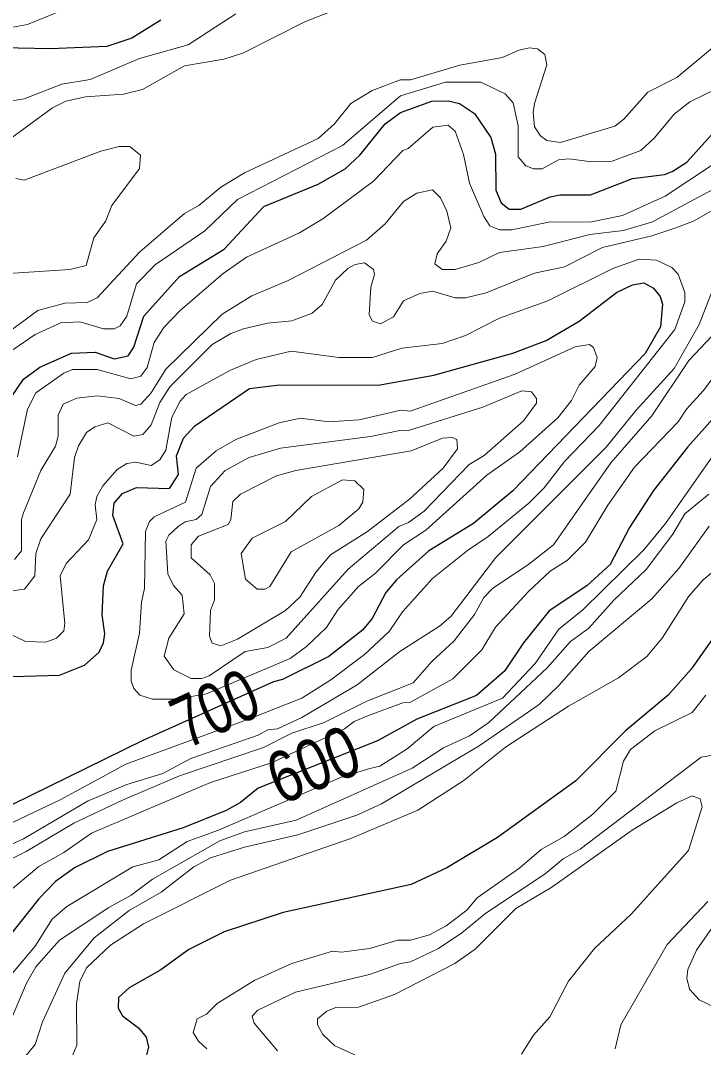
# Model space of a CAD drawing. Extents: x 577 to 602.9, y 7483.8 to 7511.6.
# Drawn here: x 592.28 to 593.349, y 7492.363 to 7493.971 of the extents above; entities that cross this region are included whole.
import ezdxf
from ezdxf.enums import TextEntityAlignment as Align

# ---------------------------------------------------------------- set-up
doc = ezdxf.new("R2010")
doc.units = 0
doc.header["$LTSCALE"] = 0.032
doc.layers.add('1', color=7, linetype='Continuous', lineweight=25)
doc.layers.add('2', color=7, linetype='Continuous', lineweight=13)
doc.layers.add('61', color=7, linetype='Continuous')

msp = doc.modelspace()

# ---------------------------------------------------------------- linework, layer by layer
at = {"layer": '1'}
for points in [[(592.499, 7493.9715), (592.4537, 7493.9429), (592.4147, 7493.9302), (592.3265, 7493.9262), (592.2247, 7493.9286), (592.2, 7493.9262), (592.1937, 7493.9326), (592.1849, 7493.9572), (592.1722, 7493.9707), (592.1651, 7493.9739)], [(592.2652, 7493.3815), (592.2843, 7493.4094), (592.3098, 7493.4284), (592.3591, 7493.4499), (592.3965, 7493.4515), (592.4259, 7493.4412), (592.4481, 7493.4459), (592.4569, 7493.4595), (592.4728, 7493.508), (592.5285, 7493.57), (592.5984, 7493.6129), (592.6605, 7493.6797), (592.7455, 7493.7147), (592.7877, 7493.7386), (592.8107, 7493.76), (592.8505, 7493.8093), (592.8744, 7493.8268), (592.9237, 7493.8443), (592.9491, 7493.8451), (592.9666, 7493.8411), (592.9904, 7493.8252), (593.0159, 7493.7879), (593.0231, 7493.7616), (593.0238, 7493.7052), (593.0318, 7493.6853), (593.0445, 7493.6757), (593.0628, 7493.6757), (593.1089, 7493.6948), (593.124, 7493.698), (593.1718, 7493.698), (593.2377, 7493.7234), (593.2878, 7493.7298), (593.2998, 7493.7346), (593.3228, 7493.7489), (593.3801, 7493.8125)], [(592.2493, 7492.9434), (592.3408, 7492.9458), (592.3798, 7492.9617), (592.4028, 7492.9823), (592.4092, 7492.9967), (592.4116, 7493.011), (592.4076, 7493.0404), (592.4092, 7493.0857), (592.4155, 7493.1088), (592.4402, 7493.1517), (592.4243, 7493.1962), (592.4259, 7493.2153), (592.4394, 7493.2304), (592.4609, 7493.24), (592.5125, 7493.2384), (592.5269, 7493.2599), (592.5237, 7493.2893), (592.5348, 7493.3171), (592.5523, 7493.3362), (592.6382, 7493.395), (592.6851, 7493.4006), (592.8394, 7493.3998), (592.9268, 7493.4157), (593.0501, 7493.4499), (593.1026, 7493.4698), (593.1543, 7493.5), (593.2123, 7493.5449), (593.2377, 7493.5573), (593.2552, 7493.5604), (593.2704, 7493.5517), (593.2807, 7493.539), (593.2847, 7493.527), (593.2815, 7493.4913), (593.2573, 7493.4498), (593.0501, 7493.2344), (592.9889, 7493.1835), (592.9189, 7493.1406), (592.868, 7493.0953), (592.8513, 7493.0754), (592.8298, 7493.0348), (592.8147, 7493.0165), (592.7622, 7492.9752), (592.6899, 7492.9394), (592.6756, 7492.9354), (592.4712, 7492.844), (592.2358, 7492.7287)], [(593.3761, 7493.3616), (593.3244, 7493.3036), (593.2704, 7493.2352), (593.233, 7493.1772), (593.2028, 7493.1191), (593.1662, 7493.0857), (593.1073, 7493.0468), (593.0668, 7492.9967), (593.0374, 7492.9521), (592.9936, 7492.914), (592.8998, 7492.8774), (592.8386, 7492.8432), (592.6517, 7492.7692), (592.6239, 7492.747), (592.6016, 7492.7343), (592.534, 7492.7072), (592.4155, 7492.6698), (592.3639, 7492.6444), (592.3344, 7492.6229), (592.3082, 7492.5959), (592.2637, 7492.5402)], [(593.3841, 7493.0332), (593.3292, 7492.9553), (593.2934, 7492.9148), (593.2266, 7492.8591), (593.1487, 7492.7804), (593.0262, 7492.6921), (592.9467, 7492.6444), (592.8911, 7492.6182), (592.6907, 7492.5744), (592.5984, 7492.5442), (592.5428, 7492.5164), (592.499, 7492.4846), (592.4497, 7492.4567), (592.433, 7492.4416), (592.4322, 7492.4249), (592.4394, 7492.413), (592.464, 7492.3939), (592.476, 7492.3796), (592.4799, 7492.3637), (592.476, 7492.3494)]]:
    msp.add_lwpolyline(points, dxfattribs=at)
at = {"layer": '2'}
for points in [[(592.2096, 7493.9867), (592.2231, 7493.9692), (592.2398, 7493.9612), (592.2676, 7493.9604), (592.2907, 7493.9644), (592.3726, 7493.9978)], [(592.8036, 7493.9994), (592.7257, 7493.9692), (592.6278, 7493.9199), (592.5976, 7493.9103), (592.5364, 7493.9), (592.4704, 7493.8626), (592.441, 7493.8554), (592.3813, 7493.8515), (592.3503, 7493.8443), (592.3297, 7493.834), (592.2557, 7493.7799)], [(592.6167, 7493.9811), (592.542, 7493.9326), (592.4656, 7493.9111), (592.3885, 7493.8785), (592.344, 7493.8714), (592.2851, 7493.8483), (592.2565, 7493.8435)], [(592.2056, 7493.4428), (592.3066, 7493.5167), (592.3487, 7493.5286), (592.3837, 7493.5294), (592.3996, 7493.5366), (592.4656, 7493.6081), (592.5364, 7493.6686), (592.5587, 7493.6813), (592.5929, 7493.7099), (592.6302, 7493.7322), (592.7455, 7493.7863), (592.771, 7493.8093), (592.7964, 7493.8411), (592.8298, 7493.861), (592.8744, 7493.8777), (592.8903, 7493.8777), (592.9674, 7493.9008), (593.0342, 7493.9127), (593.0596, 7493.9246), (593.0763, 7493.9278), (593.0891, 7493.9262), (593.1002, 7493.9175), (593.1034, 7493.9016), (593.0843, 7493.8411), (593.0819, 7493.8268), (593.0843, 7493.8046), (593.0938, 7493.7902), (593.1034, 7493.7831), (593.1248, 7493.7799), (593.2099, 7493.8054), (593.2242, 7493.8165), (593.2616, 7493.8586), (593.3069, 7493.8817), (593.3721, 7493.9358)], [(593.4485, 7493.9024), (593.3276, 7493.8435), (593.303, 7493.8244), (593.2719, 7493.7871), (593.2505, 7493.7672), (593.2059, 7493.7505), (593.1733, 7493.7497), (593.1384, 7493.7545), (593.1217, 7493.7529), (593.0962, 7493.7386), (593.0827, 7493.7386), (593.0708, 7493.7433), (593.0588, 7493.7576), (593.0588, 7493.8061), (593.0509, 7493.8419), (593.0382, 7493.8562), (593, 7493.8745), (592.9451, 7493.8745), (592.8744, 7493.8531), (592.7837, 7493.7751), (592.6191, 7493.6908), (592.5682, 7493.6415), (592.4911, 7493.5891), (592.4609, 7493.5588), (592.4458, 7493.508), (592.4354, 7493.4928), (592.4259, 7493.4881), (592.4092, 7493.4881), (592.3726, 7493.4992), (592.3424, 7493.4976), (592.3026, 7493.4793), (592.2676, 7493.4555)], [(593.4, 7493.7696), (593.2886, 7493.6956), (593.2218, 7493.6654), (593.171, 7493.6551), (593.1089, 7493.6559), (593.0485, 7493.6431), (593.0294, 7493.6431), (593.0143, 7493.6495), (593.0048, 7493.6638), (592.9825, 7493.7163), (592.973, 7493.7608), (592.9602, 7493.7974), (592.9491, 7493.8069), (592.9252, 7493.8038), (592.8863, 7493.7704), (592.8783, 7493.7672), (592.8322, 7493.7195), (592.7527, 7493.6606), (592.7161, 7493.6384), (592.6334, 7493.6002), (592.5968, 7493.5748), (592.5292, 7493.5167), (592.5038, 7493.4905), (592.4887, 7493.4666), (592.4776, 7493.4276), (592.468, 7493.4141), (592.4521, 7493.4101), (592.3996, 7493.4245), (592.3607, 7493.4245), (592.3472, 7493.4189), (592.3034, 7493.3879), (592.2907, 7493.3624), (592.2748, 7493.2877)], [(592.2724, 7493.7234), (592.2851, 7493.7211), (592.4052, 7493.7664), (592.4338, 7493.7735), (592.4505, 7493.7735), (592.4672, 7493.76), (592.4656, 7493.7394), (592.4227, 7493.6813), (592.4132, 7493.6574), (592.3941, 7493.6304), (592.3821, 7493.5875), (592.3567, 7493.5811), (592.2605, 7493.5748)], [(592.27, 7493.1271), (592.2812, 7493.1406), (592.2812, 7493.1899), (592.2843, 7493.2002), (592.3114, 7493.2662), (592.3344, 7493.3044), (592.3384, 7493.3203), (592.3384, 7493.3529), (592.3464, 7493.3704), (592.3678, 7493.3799), (592.3996, 7493.3831), (592.4338, 7493.3791), (592.4593, 7493.368), (592.468, 7493.3704), (592.4839, 7493.3879), (592.507, 7493.4253), (592.5952, 7493.5111), (592.6414, 7493.5398), (592.6986, 7493.5636), (592.8211, 7493.6272), (592.8505, 7493.6527), (592.8791, 7493.6877), (592.8998, 7493.7004), (592.9245, 7493.706), (592.9372, 7493.6932), (592.9467, 7493.6726), (592.9531, 7493.6463), (592.9459, 7493.6256), (592.9316, 7493.6058), (592.9284, 7493.5899), (592.9396, 7493.5811), (592.9602, 7493.5811), (592.9968, 7493.5922), (593.0294, 7493.6074), (593.0978, 7493.6169), (593.171, 7493.636), (593.2234, 7493.6423), (593.2688, 7493.6559), (593.3992, 7493.7258)], [(592.2629, 7493.0778), (592.2859, 7493.0809), (592.3018, 7493.1016), (592.3034, 7493.1366), (592.3114, 7493.1597), (592.3575, 7493.2296), (592.3639, 7493.2869), (592.3702, 7493.3052), (592.3829, 7493.3259), (592.3957, 7493.3346), (592.4163, 7493.341), (592.4569, 7493.3203), (592.4712, 7493.3227), (592.4839, 7493.3378), (592.4974, 7493.3728), (592.5133, 7493.3974), (592.5793, 7493.4634), (592.6088, 7493.4809), (592.6286, 7493.4881), (592.666, 7493.4968), (592.7042, 7493.5008), (592.736, 7493.5127), (592.7519, 7493.5262), (592.7726, 7493.5644), (592.7917, 7493.5827), (592.8036, 7493.5891), (592.8179, 7493.5915), (592.8322, 7493.5811), (592.8338, 7493.5732), (592.8282, 7493.5533), (592.8251, 7493.5103), (592.8306, 7493.5), (592.8433, 7493.496), (592.8632, 7493.5072), (592.8791, 7493.5318), (592.9046, 7493.5437), (592.9245, 7493.5469), (592.9602, 7493.5366), (592.9761, 7493.5366), (593.0087, 7493.5445), (593.0843, 7493.5755), (593.1312, 7493.5851), (593.1908, 7493.6153), (593.268, 7493.6336), (593.3053, 7493.6463), (593.334, 7493.6574), (593.3944, 7493.6916)], [(592.1643, 7492.6667), (592.3416, 7492.7509), (592.4442, 7492.8066), (592.6405, 7492.8787), (592.7201, 7492.91), (592.7654, 7492.9386), (592.8179, 7492.9784), (592.8569, 7493.0142), (592.8775, 7493.0452), (592.9245, 7493.0976), (592.9793, 7493.1414), (593.0119, 7493.1629), (593.0755, 7493.2153), (593.0994, 7493.2392), (593.1312, 7493.2805), (593.1853, 7493.337), (593.3037, 7493.4873), (593.3197, 7493.5302), (593.3197, 7493.5453), (593.3093, 7493.574), (593.299, 7493.5843), (593.2751, 7493.5954), (593.2481, 7493.597), (593.2067, 7493.5827), (593.105, 7493.5318), (593.0294, 7493.5048), (592.9761, 7493.4777), (592.9396, 7493.465), (592.8767, 7493.4579), (592.8306, 7493.4435), (592.7781, 7493.4435), (592.7034, 7493.4531), (592.6485, 7493.4404), (592.608, 7493.4237), (592.5388, 7493.3855), (592.5292, 7493.3752), (592.5165, 7493.3497), (592.507, 7493.298), (592.4974, 7493.2829), (592.4839, 7493.2742), (592.4601, 7493.2797), (592.4458, 7493.2774), (592.4306, 7493.2678), (592.4084, 7493.2424), (592.3988, 7493.2257), (592.3965, 7493.2129), (592.3988, 7493.1899), (592.3861, 7493.1581), (592.3511, 7493.1207), (592.3416, 7493.1016), (592.3487, 7493.0269), (592.3472, 7493.0157), (592.336, 7493.0038), (592.3193, 7492.9975), (592.2875, 7492.999), (592.2334, 7493.0245)], [(593.3737, 7493.5771), (593.3419, 7493.4952)], [(593.3419, 7493.4952), (593.303, 7493.4261), (593.2433, 7493.3608), (593.1964, 7493.3028), (593.0238, 7493.1302), (592.9531, 7493.038), (592.9356, 7493.0229), (592.8736, 7492.9831), (592.8068, 7492.9307), (592.7201, 7492.8798), (592.6819, 7492.8623), (592.6668, 7492.8607), (592.6517, 7492.8519), (592.5459, 7492.8154)], [(593.3801, 7493.496), (593.326, 7493.4388), (593.268, 7493.3521), (593.2036, 7493.2782), (593.1137, 7493.1501), (593.0755, 7493.1199), (593.0183, 7493.0817)], [(592.7869, 7492.8623), (592.802, 7492.8734), (592.8243, 7492.8829), (592.8783, 7492.9028), (592.8903, 7492.9036), (592.9563, 7492.9402), (593.0016, 7492.9855), (593.0231, 7493.0213), (593.0747, 7493.077), (593.1089, 7493.1088), (593.136, 7493.1263), (593.1638, 7493.1541), (593.1988, 7493.2122), (593.2409, 7493.2718), (593.3093, 7493.3426), (593.322, 7493.3624), (593.3483, 7493.3911), (593.3928, 7493.4499)], [(592.8263, 7492.8002), (592.8418, 7492.8034), (592.8847, 7492.8305), (592.9268, 7492.8655), (593.0342, 7492.91), (593.0851, 7492.9641), (593.1224, 7493.0181), (593.1598, 7493.0483), (593.2552, 7493.1422), (593.2894, 7493.1835), (593.396, 7493.3362)], [(593.357, 7493.2296), (593.3197, 7493.1986), (593.3006, 7493.1668), (593.2592, 7493.1112), (593.2083, 7493.0635), (593.1694, 7493.0197), (593.1407, 7492.999), (593.1042, 7492.9577), (593.0127, 7492.8718), (592.9825, 7492.8511), (592.9419, 7492.8321), (592.8926, 7492.8003), (592.7113, 7492.7191), (592.6302, 7492.7009), (592.5913, 7492.6865), (592.4863, 7492.6269), (592.4529, 7492.6015), (592.4179, 7492.5824), (592.3408, 7492.5315), (592.3034, 7492.4893), (592.2891, 7492.4639), (592.2581, 7492.3915)], [(592.3138, 7492.4035), (592.3487, 7492.4798), (592.3949, 7492.5347), (592.4497, 7492.5776), (592.4998, 7492.6062), (592.5507, 7492.646), (592.577, 7492.6603), (592.6302, 7492.677), (592.7137, 7492.6961), (592.806, 7492.7271), (592.8449, 7492.7446), (592.9976, 7492.8352), (593.0914, 7492.9004), (593.1224, 7492.9299), (593.1694, 7492.9831), (593.268, 7493.0658), (593.3101, 7493.1128), (593.3578, 7493.1795)], [(592.3615, 7492.3518), (592.3678, 7492.3669), (592.367, 7492.4321), (592.3726, 7492.4663), (592.3829, 7492.4877), (592.4203, 7492.5235), (592.472, 7492.5569), (592.608, 7492.6253), (592.7964, 7492.6905), (592.9014, 7492.735), (592.9738, 7492.7812), (593.039, 7492.8336), (593.1376, 7492.8973), (593.2155, 7492.9418), (593.26, 7492.9752), (593.2839, 7493.0038), (593.326, 7493.0698), (593.3483, 7493.0953), (593.3896, 7493.1295)], [(593.0183, 7493.0817), (593.0048, 7493.0674), (592.9904, 7493.0412), (592.9586, 7492.9998), (592.9237, 7492.9672), (592.8942, 7492.9338), (592.8219, 7492.9052), (592.7551, 7492.8718), (592.7042, 7492.8551), (592.6597, 7492.8329), (592.5285, 7492.7883), (592.4394, 7492.7502), (592.3631, 7492.7144), (592.2883, 7492.6698), (592.2334, 7492.6428)], [(593.3523, 7492.9148), (593.3308, 7492.8877), (593.2727, 7492.8591), (593.2346, 7492.8297), (593.2234, 7492.8114), (593.2115, 7492.7645), (593.1757, 7492.7287), (593.1304, 7492.6937), (593.0946, 7492.673), (593.0612, 7492.6444), (592.9944, 7492.5975), (592.9785, 7492.5784), (592.9459, 7492.5537), (592.9197, 7492.5394), (592.8903, 7492.5315), (592.8704, 7492.5315), (592.8258, 7492.518), (592.7821, 7492.5124), (592.7678, 7492.514), (592.7042, 7492.4949), (592.6461, 7492.4687), (592.5873, 7492.4321), (592.5706, 7492.4154), (592.5563, 7492.4082), (592.5499, 7492.3868), (592.5579, 7492.3732), (592.5714, 7492.3613)], [(592.2271, 7492.5792), (592.3082, 7492.6468), (592.3472, 7492.6683), (592.3909, 7492.6985), (592.577, 7492.778), (592.6724, 7492.809), (592.7869, 7492.8623)], [(592.5459, 7492.8154), (592.5022, 7492.7923), (592.4458, 7492.7748), (592.3845, 7492.7486), (592.2843, 7492.6897), (592.2223, 7492.6619)], [(592.6819, 7492.3581), (592.6453, 7492.4011), (592.6422, 7492.4122), (592.6509, 7492.4217), (592.7098, 7492.4496), (592.8258, 7492.4774), (592.8744, 7492.4949), (592.8903, 7492.4973), (592.934, 7492.518), (592.9706, 7492.5426), (593.0079, 7492.5736), (593.101, 7492.6349), (593.1288, 7492.6587), (593.1558, 7492.6738), (593.3451, 7492.8177), (593.3626, 7492.8209)], [(592.1786, 7492.378), (592.2207, 7492.4154), (592.247, 7492.4567), (592.3026, 7492.5219), (592.3289, 7492.5641), (592.3519, 7492.584), (592.4553, 7492.646), (592.4959, 7492.6571), (592.5404, 7492.6857), (592.5897, 7492.7032), (592.7805, 7492.7859), (592.8263, 7492.8002)], [(593.0636, 7492.3526), (593.0827, 7492.3828), (593.1081, 7492.4114), (593.1376, 7492.4671), (593.1781, 7492.518), (593.2354, 7492.572), (593.3252, 7492.6714), (593.3467, 7492.7398), (593.3435, 7492.7525), (593.3308, 7492.7573), (593.3069, 7492.7462), (593.237, 7492.7032), (593.1113, 7492.6142), (593.0549, 7492.5808), (592.9912, 7492.5172), (592.9594, 7492.4949), (592.8648, 7492.4464), (592.8084, 7492.4265), (592.7734, 7492.4257), (592.7591, 7492.4202), (592.7447, 7492.4082), (592.7447, 7492.3987), (592.7527, 7492.3836), (592.7718, 7492.3661), (592.8028, 7492.3518)], [(593.3658, 7492.4265), (593.3419, 7492.4376), (593.3268, 7492.4543), (593.3228, 7492.4718), (593.3244, 7492.4854), (593.3379, 7492.5156), (593.4596, 7492.6905)], [(593.3554, 7492.5919), (593.2918, 7492.5243), (593.2195, 7492.3987), (593.2107, 7492.3613)], [(592.2851, 7492.347), (592.3026, 7492.3677), (592.3138, 7492.4035)]]:
    msp.add_lwpolyline(points, dxfattribs=at)
for points in [[(592.7765, 7493.0483), (592.7583, 7493.0205), (592.7272, 7492.9911), (592.7018, 7492.972), (592.5707, 7492.9169), (592.5229, 7492.9084), (592.4863, 7492.9084), (592.4664, 7492.9148), (592.4569, 7492.9251), (592.4529, 7492.937), (592.4529, 7492.9537), (592.4656, 7493.0118), (592.4688, 7493.0603), (592.4736, 7493.0817), (592.4752, 7493.1708), (592.4815, 7493.1867), (592.4887, 7493.1939), (592.538, 7493.2169), (592.5547, 7493.2702), (592.5857, 7493.2972), (592.6167, 7493.3147), (592.6843, 7493.341), (592.7177, 7493.3481), (592.7622, 7493.3426), (592.8099, 7493.3457), (592.8751, 7493.3608), (592.8895, 7493.3593), (593.0541, 7493.4173), (593.1479, 7493.4602), (593.1702, 7493.4634), (593.1765, 7493.4587), (593.1821, 7493.4435), (593.1789, 7493.4292), (593.1543, 7493.3998), (593.1423, 7493.376), (593.1209, 7493.3489), (593.0612, 7493.2956), (593.0095, 7493.2591), (592.9141, 7493.1732), (592.8791, 7493.1501), (592.8354, 7493.1056), (592.8084, 7493.0849)], [(592.6867, 7493.3012), (592.8274, 7493.3195), (592.8759, 7493.3298), (592.8871, 7493.329), (593.0032, 7493.3656), (593.0644, 7493.3911), (593.0795, 7493.3895), (593.0875, 7493.3791), (593.0875, 7493.372), (593.0668, 7493.3442), (593.0056, 7493.2901), (592.9817, 7493.2758), (592.9117, 7493.2026), (592.8871, 7493.1851), (592.872, 7493.1788), (592.7925, 7493.112), (592.6954, 7493.0038), (592.6668, 7492.9895), (592.631, 7492.9831), (592.5746, 7492.945), (592.5634, 7492.941), (592.5467, 7492.941), (592.5197, 7492.9545), (592.5046, 7492.976), (592.5118, 7493.0038), (592.5356, 7493.042), (592.5324, 7493.0714), (592.5189, 7493.0865), (592.5102, 7493.1048), (592.507, 7493.1557), (592.5118, 7493.1652), (592.5261, 7493.1788), (592.5372, 7493.1859), (592.5547, 7493.1899), (592.5634, 7493.1978), (592.577, 7493.2416), (592.6, 7493.2662), (592.6374, 7493.2869)], [(592.7105, 7493.2662), (592.8911, 7493.2972), (592.9404, 7493.3171), (592.9555, 7493.3179), (592.9626, 7493.3147), (592.9634, 7493.3004), (592.9411, 7493.2702), (592.8887, 7493.2217), (592.8227, 7493.1708), (592.7646, 7493.1342), (592.7424, 7493.108), (592.7169, 7493.0682), (592.6946, 7493.0475), (592.6191, 7493.0022), (592.5929, 7492.9919), (592.5793, 7492.9959), (592.5754, 7493.007), (592.577, 7493.0475), (592.5833, 7493.0642), (592.5833, 7493.0897), (592.5762, 7493.1032), (592.5467, 7493.1295), (592.5467, 7493.1501), (592.5579, 7493.1636), (592.6048, 7493.1819), (592.6088, 7493.1899), (592.6119, 7493.2177), (592.6239, 7493.2296), (592.6803, 7493.2583)], [(592.6318, 7493.0962), (592.6501, 7493.0809), (592.662, 7493.0809), (592.67, 7493.0849), (592.7034, 7493.139), (592.7781, 7493.1803), (592.8091, 7493.2066), (592.8155, 7493.2169), (592.8171, 7493.2368), (592.8028, 7493.2503), (592.7837, 7493.2519), (592.7352, 7493.2257), (592.6946, 7493.1867), (592.6422, 7493.1605), (592.6247, 7493.1366)]]:
    msp.add_lwpolyline(points, close=True, dxfattribs=at)

# ---------------------------------------------------------------- texts
at = {"layer": '61'}
for s, rotation, width, p in [('700', 24.825, 0.75, (592.6008, 7492.8583)), ('600', 22.073, 0.8, (592.7529, 7492.7692))]:
    msp.add_text(s, height=0.08, rotation=rotation, dxfattribs=dict(at, width=width)).set_placement(p, align=Align.CENTER)

doc.saveas('drawing.dxf')
